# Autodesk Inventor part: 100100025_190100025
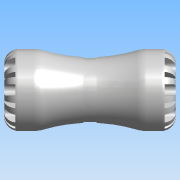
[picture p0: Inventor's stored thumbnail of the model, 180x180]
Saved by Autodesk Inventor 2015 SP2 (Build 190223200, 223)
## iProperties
Created: 2016-12
Part Number: 100100025_190100025
Material: PVC-Piping
Description: PLASSON COUPLER 25X25 SERIES 1
Document SubType Name: Modeling
Designer: KIM
Mass: 95.2094 g
Surface Area: 200.83 cm^2
Volume: 68.0067 cm^3
Density: 1.4 g/cm^3
Appearance: Smooth - White
ILogicFactory: False
Author: KIM
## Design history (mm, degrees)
derived "1001.ipt"
feature "Solid1::1001.ipt"
tag "TaggingFeature1"
body "Solid1"
other parameters: "d2" = 48, "d4" = 2.08333, "d11" = 6.3, "d13" = 6.3, "d14" = 0, "d16" = 360 deg, "d18" = 8 deg, "d19" = 0.5, "d20" = 8 deg, "d21" = 0.5, "d23" = 0, "d25" = 360 deg, "d27" = 18.8, "d28" = 6.25, "d29" = 7.5, "d30" = 7.5, "d31" = 0, "d33" = 0, "d37" = 19.6, "d38" = 0.47, "d43" = 3.125, "d44" = 25, "d45" = 19.6, "d46" = 37.6, "d47" = 47, "d48" = 98, "d50" = 360 deg, "d54" = 0.5, "d_" = 25, "E_" = 47, "H_" = 98, "l_" = 48, "d12" = 31.25, "d42" = 47, "d52" = 7.875
